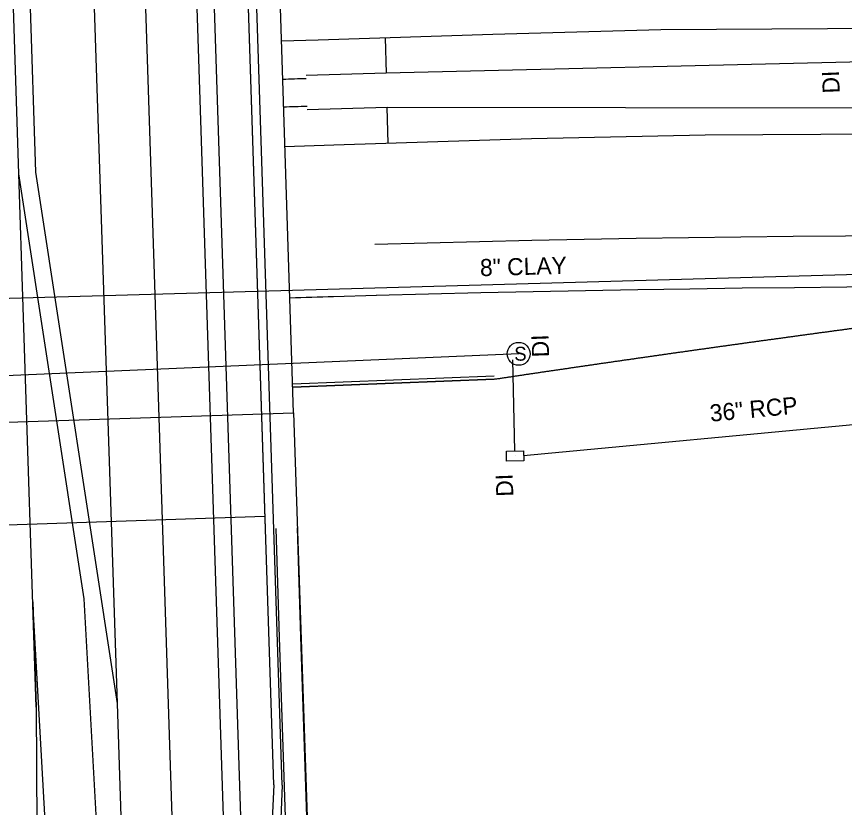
# Model space of a CAD drawing. Extents: x 1627482 to 1629573, y 760826 to 766301.
# Drawn here: x 1628494.4 to 1628688.3, y 761152 to 761337.2 of the extents above; entities that cross this region are included whole.
import ezdxf

# ---------------------------------------------------------------- set-up
doc = ezdxf.new("R2010")
doc.units = 0
for name, color, linetype in [('Exist Building', 7, 'Continuous'), ('Exist Guardrail', 7, 'Continuous'), ('Exist Other Culture Fence Line', 7, 'Continuous'), ('Exist Roads Change in Surface', 7, 'Continuous'), ('Exist Roads Concrete Median Barrier', 7, 'Continuous'), ('Exist Roads Curbs', 7, 'Continuous'), ('Exist Roads EOP', 7, 'Continuous'), ('Exist Roads EOP Other', 7, 'Continuous'), ('Exist Roads EOT', 7, 'Continuous'), ('Exist Structure Major Deck Tunnel Box Culvert', 7, 'Continuous'), ('Exist Structure Minor Drop Inlet', 7, 'Continuous'), ('Exist Structure Minor Drop Inlet Text', 7, 'Continuous'), ('Exist Structure Minor Pipes RCP 36 Inch', 7, 'Continuous'), ('Exist Structure Minor Pipes RCP 36 Inch Text', 7, 'Continuous'), ('Exist Structure Minor Storm Sewer Manhole CELL', 7, 'Continuous'), ('Exist Utilities Sanitary Sewer UG Line', 7, 'Continuous'), ('Exist Utilities Sanitary Sewer UG Line Text', 7, 'Continuous')]:
    doc.layers.add(name, color=color, linetype=linetype)

msp = doc.modelspace()

# ---------------------------------------------------------------- linework, layer by layer
at = {"layer": 'Exist Building'}
msp.add_line((1628606.22, 761252.34), (1628559.06, 761250.48), dxfattribs=at)
at = {"layer": 'Exist Guardrail'}
for p, q in [((1628781.08, 761328.69), (1628580.92, 761324.01)), ((1628580.92, 761324.01), (1628562.18, 761323.44)), ((1628562.42, 761315.45), (1628581.16, 761316.02)), ((1628581.16, 761316.02), (1628780.98, 761315.82)), ((1628559.25, 761244.45), (1628565.74, 761050.82))]:
    msp.add_line(p, q, dxfattribs=at)
at = {"layer": 'Exist Other Culture Fence Line'}
msp.add_line((1628559.06, 761250.48), (1628606.22, 761252.34), dxfattribs=at)
at = {"layer": 'Exist Roads Change in Surface'}
msp.add_line((1628469.59, 761217.51), (1628552.54, 761220.22), dxfattribs=at)
at = {"layer": 'Exist Roads Concrete Median Barrier'}
msp.add_line((1628559.03, 761251.23), (1628606.19, 761253.08), dxfattribs=at)
for centre, radius, start, end in [((1628734.38, 755622.79), 5702.5, 91.73016, 91.78547), ((1628734.45, 755621.3), 5697.5, 91.73044, 91.78564)]:
    msp.add_arc(centre, radius, start, end, dxfattribs=at)
at = {"layer": 'Exist Roads Curbs'}
for p, q in [((1628494.89, 761300.41), (1628489.17, 761474.17)), ((1628498.88, 761300.78), (1628493.3, 761474.03)), ((1628556.6, 761157.27), (1628547.12, 761447.2)), ((1628510.15, 761200.86), (1628494.89, 761300.41)), ((1628517.96, 761176.34), (1628498.88, 761300.78)), ((1628517.25, 761074.16), (1628510.15, 761200.86)), ((1628521.3, 761074.34), (1628517.96, 761176.34)), ((1628556.6, 761157.27), (1628551.87, 761056.98))]:
    msp.add_line(p, q, dxfattribs=at)
at = {"layer": 'Exist Roads EOP'}
for p, q in [((1628552.64, 761217.25), (1628545.12, 761447.13)), ((1628580.67, 761332.3), (1628580.92, 761324.01)), ((1628581.42, 761307.55), (1628581.16, 761316.02)), ((1628578.62, 761271.9), (1628568.62, 761271.62)), ((1628559.06, 761250.48), (1628606.22, 761252.34)), ((1628554.6, 761157.29), (1628549.88, 761057.08))]:
    msp.add_line(p, q, dxfattribs=at)
for points in [[(1628556.41, 761331.55), (1628565, 761331.81), (1628605.9, 761333.09), (1628645.26, 761334.25), (1628684.32, 761334.42), (1628722.49, 761334.84), (1628759.73, 761334.87), (1628801.86, 761334.52), (1628843.35, 761333.75), (1628879.66, 761332.87), (1628923.38, 761331.36), (1628962.91, 761330.16), (1629003.68, 761327.91), (1629042.13, 761325.5), (1629086.77, 761322.98), (1629123.25, 761320.47), (1629162.51, 761317.6), (1629197.83, 761314.95), (1629240.1, 761311.53), (1629281.42, 761307.61), (1629317.78, 761304.3), (1629359.27, 761299.98)], [(1629359.92, 761275.77), (1629325.58, 761279.44), (1629285.36, 761283.43), (1629253.28, 761286.62), (1629207.5, 761290.58), (1629169.61, 761293.54), (1629137.97, 761295.66), (1629088.81, 761299.11), (1629055.49, 761300.99), (1629013.39, 761302.95), (1628973.15, 761305.14), (1628929.3, 761306.72), (1628900.83, 761307.84), (1628855.03, 761309.09), (1628808.53, 761309.63), (1628774.64, 761309.86), (1628733.17, 761309.91), (1628696.26, 761309.68), (1628655.61, 761309.45), (1628614.95, 761308.59), (1628568.68, 761307.15), (1628557.22, 761306.74)]]:
    msp.add_lwpolyline(points, dxfattribs=at)
for centre, radius, start, end in [((1628734.41, 755622.04), 5652, 83.63613, 91.57952), ((1628724.69, 755622.3), 5651.48, 91.58246, 91.68639)]:
    msp.add_arc(centre, radius, start, end, dxfattribs=at)
for points in [[(1628670.34, 761261.56), (1628671.21, 761261.68), (1628672.08, 761261.79), (1628672.94, 761261.91), (1628673.81, 761262.03), (1628674.68, 761262.15), (1628675.55, 761262.27), (1628676.42, 761262.39), (1628677.28, 761262.51), (1628678.15, 761262.63), (1628679.02, 761262.75), (1628679.89, 761262.86), (1628680.76, 761262.98), (1628681.62, 761263.1), (1628682.49, 761263.22), (1628683.36, 761263.34), (1628684.23, 761263.45), (1628685.1, 761263.57), (1628685.97, 761263.69), (1628686.83, 761263.81), (1628687.7, 761263.92), (1628688.57, 761264.04), (1628689.44, 761264.16), (1628690.31, 761264.27), (1628691.18, 761264.39), (1628692.05, 761264.51), (1628692.91, 761264.62), (1628693.78, 761264.74), (1628694.65, 761264.85), (1628695.52, 761264.97), (1628696.39, 761265.09), (1628697.26, 761265.2), (1628698.13, 761265.32), (1628699, 761265.43), (1628699.87, 761265.55), (1628700.73, 761265.66), (1628701.6, 761265.78), (1628702.47, 761265.89), (1628703.34, 761266.01), (1628704.21, 761266.12), (1628705.08, 761266.24), (1628705.95, 761266.35), (1628706.82, 761266.46), (1628707.69, 761266.58), (1628708.56, 761266.69), (1628709.43, 761266.81), (1628710.3, 761266.92), (1628711.17, 761267.03), (1628712.04, 761267.15), (1628712.9, 761267.26), (1628713.77, 761267.37), (1628714.64, 761267.48), (1628715.51, 761267.6), (1628716.38, 761267.71), (1628717.25, 761267.82), (1628718.12, 761267.93), (1628718.99, 761268.05), (1628719.86, 761268.16), (1628720.73, 761268.27), (1628721.6, 761268.38), (1628722.47, 761268.49), (1628723.34, 761268.61), (1628724.21, 761268.72), (1628725.08, 761268.83), (1628725.95, 761268.94), (1628726.82, 761269.05), (1628727.69, 761269.16), (1628728.56, 761269.27), (1628729.43, 761269.38), (1628730.3, 761269.49), (1628731.17, 761269.6), (1628732.04, 761269.71), (1628732.91, 761269.82), (1628734.65, 761270.04)], [(1628606.22, 761252.34), (1628607.09, 761252.46), (1628607.95, 761252.59), (1628608.82, 761252.72), (1628609.68, 761252.85), (1628610.55, 761252.98), (1628611.41, 761253.11), (1628612.28, 761253.24), (1628613.14, 761253.37), (1628614.01, 761253.5), (1628614.87, 761253.62), (1628615.74, 761253.75), (1628616.6, 761253.88), (1628617.47, 761254.01), (1628618.34, 761254.14), (1628619.2, 761254.26), (1628620.07, 761254.39), (1628620.93, 761254.52), (1628621.8, 761254.65), (1628622.66, 761254.77), (1628623.53, 761254.9), (1628624.4, 761255.03), (1628625.26, 761255.15), (1628626.13, 761255.28), (1628626.99, 761255.41), (1628627.86, 761255.53), (1628628.73, 761255.66), (1628629.59, 761255.78), (1628630.46, 761255.91), (1628631.32, 761256.04), (1628632.19, 761256.16), (1628633.06, 761256.29), (1628633.92, 761256.41), (1628634.79, 761256.54), (1628635.66, 761256.66), (1628636.52, 761256.79), (1628637.39, 761256.91), (1628638.26, 761257.04), (1628639.12, 761257.16), (1628639.99, 761257.29), (1628640.85, 761257.41), (1628641.72, 761257.53), (1628642.59, 761257.66), (1628643.45, 761257.78), (1628644.32, 761257.91), (1628645.19, 761258.03), (1628646.06, 761258.15), (1628646.92, 761258.28), (1628647.79, 761258.4), (1628648.66, 761258.52), (1628649.52, 761258.65), (1628650.39, 761258.77), (1628651.26, 761258.89), (1628652.12, 761259.01), (1628652.99, 761259.14), (1628653.86, 761259.26), (1628654.73, 761259.38), (1628655.59, 761259.5), (1628656.46, 761259.62), (1628657.33, 761259.75), (1628658.19, 761259.87), (1628659.06, 761259.99), (1628659.93, 761260.11), (1628660.8, 761260.23), (1628661.66, 761260.35), (1628662.53, 761260.47), (1628663.4, 761260.59), (1628664.27, 761260.71), (1628665.13, 761260.84), (1628666, 761260.96), (1628666.87, 761261.08), (1628667.74, 761261.2), (1628668.6, 761261.32), (1628669.47, 761261.44), (1628670.34, 761261.56)]]:
    msp.add_spline(points, degree=3, dxfattribs=at)
at = {"layer": 'Exist Roads EOP Other'}
for p, q in [((1628554.6, 761157.29), (1628545.12, 761447.13)), ((1628560.97, 761191.99), (1628560.14, 761217.5)), ((1628555.97, 761191.83), (1628555.14, 761217.34)), ((1628561.38, 761026.57), (1628555.97, 761191.83)), ((1628566.5, 761022.88), (1628560.97, 761191.99))]:
    msp.add_line(p, q, dxfattribs=at)
at = {"layer": 'Exist Roads EOT'}
for p, q in [((1628548.94, 760963.28), (1628522.34, 761776.56)), ((1628517.96, 761176.34), (1628504.42, 761590.36)), ((1628533.81, 761058.82), (1628516.47, 761589.01)), ((1628537.13, 761446.87), (1628549.88, 761057.08)), ((1628498.98, 761175.48), (1628494.89, 761300.41)), ((1628506.52, 761051.21), (1628498.17, 761200.18)), ((1628498.17, 761200.18), (1628498.98, 761175.48)), ((1628498.98, 761175.48), (1628499.69, 761050.83))]:
    msp.add_line(p, q, dxfattribs=at)
msp.add_arc((1628734.41, 755622.04), 5664, 83.65296, 91.57952, dxfattribs=at)
at = {"layer": 'Exist Structure Major Deck Tunnel Box Culvert'}
for p, q in [((1628559.25, 761244.45), (1628554.37, 761393.87)), ((1628461.31, 761241.25), (1628559.25, 761244.45))]:
    msp.add_line(p, q, dxfattribs=at)
at = {"layer": 'Exist Structure Minor Drop Inlet'}
for p, q in [((1628609.19, 761258.2), (1628609.19, 761258.2)), ((1628609.19, 761258.2), (1628609.19, 761258.2)), ((1628610.55, 761259.61), (1628610.55, 761259.61)), ((1628610.55, 761259.61), (1628610.55, 761259.61)), ((1628610.58, 761258.23), (1628610.58, 761258.23)), ((1628610.58, 761258.23), (1628610.58, 761258.23)), ((1628611.96, 761258.26), (1628611.96, 761258.26)), ((1628611.96, 761258.26), (1628611.96, 761258.26)), ((1628610.61, 761256.84), (1628610.61, 761256.84)), ((1628610.61, 761256.84), (1628610.61, 761256.84)), ((1628611.08, 761235.53), (1628611.08, 761235.53)), ((1628611.08, 761235.53), (1628611.08, 761235.53)), ((1628609.1, 761234.32), (1628609.1, 761234.32)), ((1628609.1, 761234.32), (1628609.1, 761234.32)), ((1628611.1, 761234.37), (1628611.1, 761234.37)), ((1628611.1, 761234.37), (1628611.1, 761234.37)), ((1628611.13, 761233.2), (1628611.13, 761233.2)), ((1628611.13, 761233.2), (1628611.13, 761233.2)), ((1628613.1, 761234.41), (1628613.1, 761234.41)), ((1628613.1, 761234.41), (1628613.1, 761234.41))]:
    msp.add_line(p, q, dxfattribs=at)
msp.add_lwpolyline([(1628613.13, 761233.24), (1628609.13, 761233.16), (1628609.08, 761235.49), (1628613.08, 761235.58), (1628613.13, 761233.24), (1628613.13, 761233.24)], dxfattribs=at)
at = {"layer": 'Exist Structure Minor Pipes RCP 36 Inch'}
for p, q in [((1628611.96, 761258.26), (1628406.07, 761249.5)), ((1628611.08, 761235.53), (1628610.61, 761256.84)), ((1628753.44, 761247.61), (1628613.1, 761234.41))]:
    msp.add_line(p, q, dxfattribs=at)
at = {"layer": 'Exist Structure Minor Storm Sewer Manhole CELL'}
msp.add_circle((1628611.96, 761258.26), 2.69, dxfattribs=at)
at = {"layer": 'Exist Utilities Sanitary Sewer UG Line'}
msp.add_lwpolyline([(1628329.76, 761266.71), (1628835.08, 761281), (1629133.02, 761267.83), (1629359.44, 761245.02)], dxfattribs=at)

# ---------------------------------------------------------------- texts
at = {"layer": 'Exist Structure Minor Drop Inlet Text'}
for rotation, p in [(92.2582, (1628687.17, 761319.32)), (92.0309, (1628619.11, 761257.52)), (92.1194, (1628610.73, 761224.88))]:
    msp.add_text('DI', height=4, rotation=rotation, dxfattribs=at).set_placement(p)
at = {"layer": 'Exist Structure Minor Pipes RCP 36 Inch Text'}
msp.add_text('36" RCP', height=4, rotation=5.3739, dxfattribs=at).set_placement((1628656.91, 761242.35))
at = {"layer": 'Exist Structure Minor Storm Sewer Manhole CELL'}
msp.add_text('S', height=3.25, dxfattribs=at).set_placement((1628610.93, 761256.66))
at = {"layer": 'Exist Utilities Sanitary Sewer UG Line Text'}
msp.add_text('8" CLAY', height=4, rotation=1.6197, dxfattribs=at).set_placement((1628602.95, 761276.44))

doc.saveas('drawing.dxf')
